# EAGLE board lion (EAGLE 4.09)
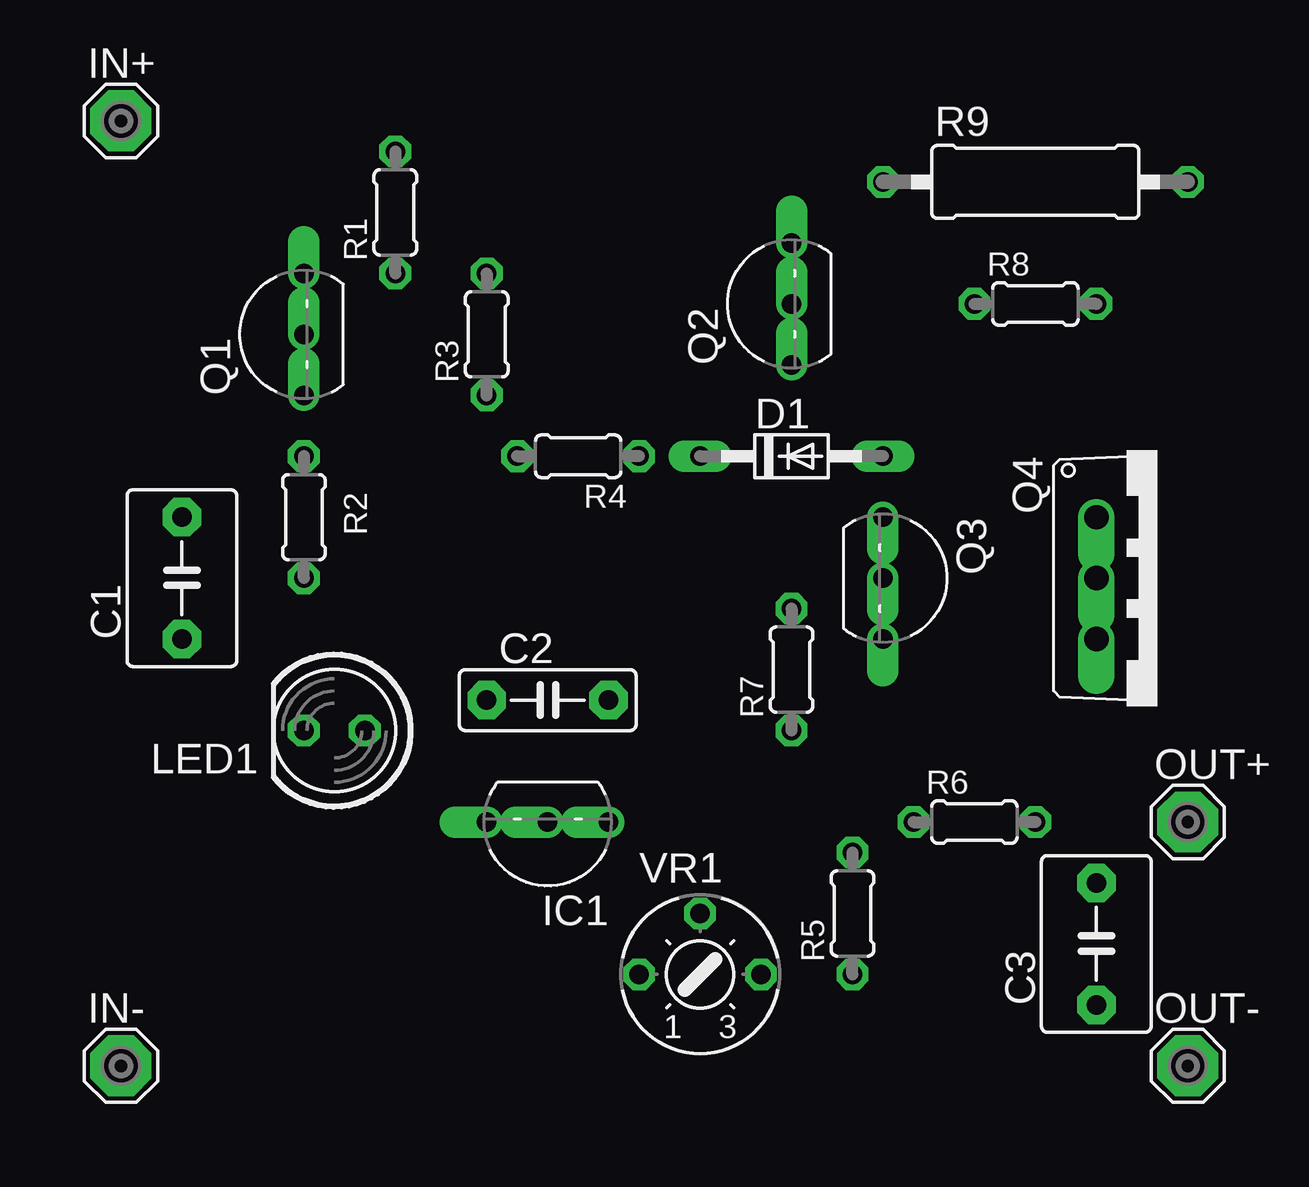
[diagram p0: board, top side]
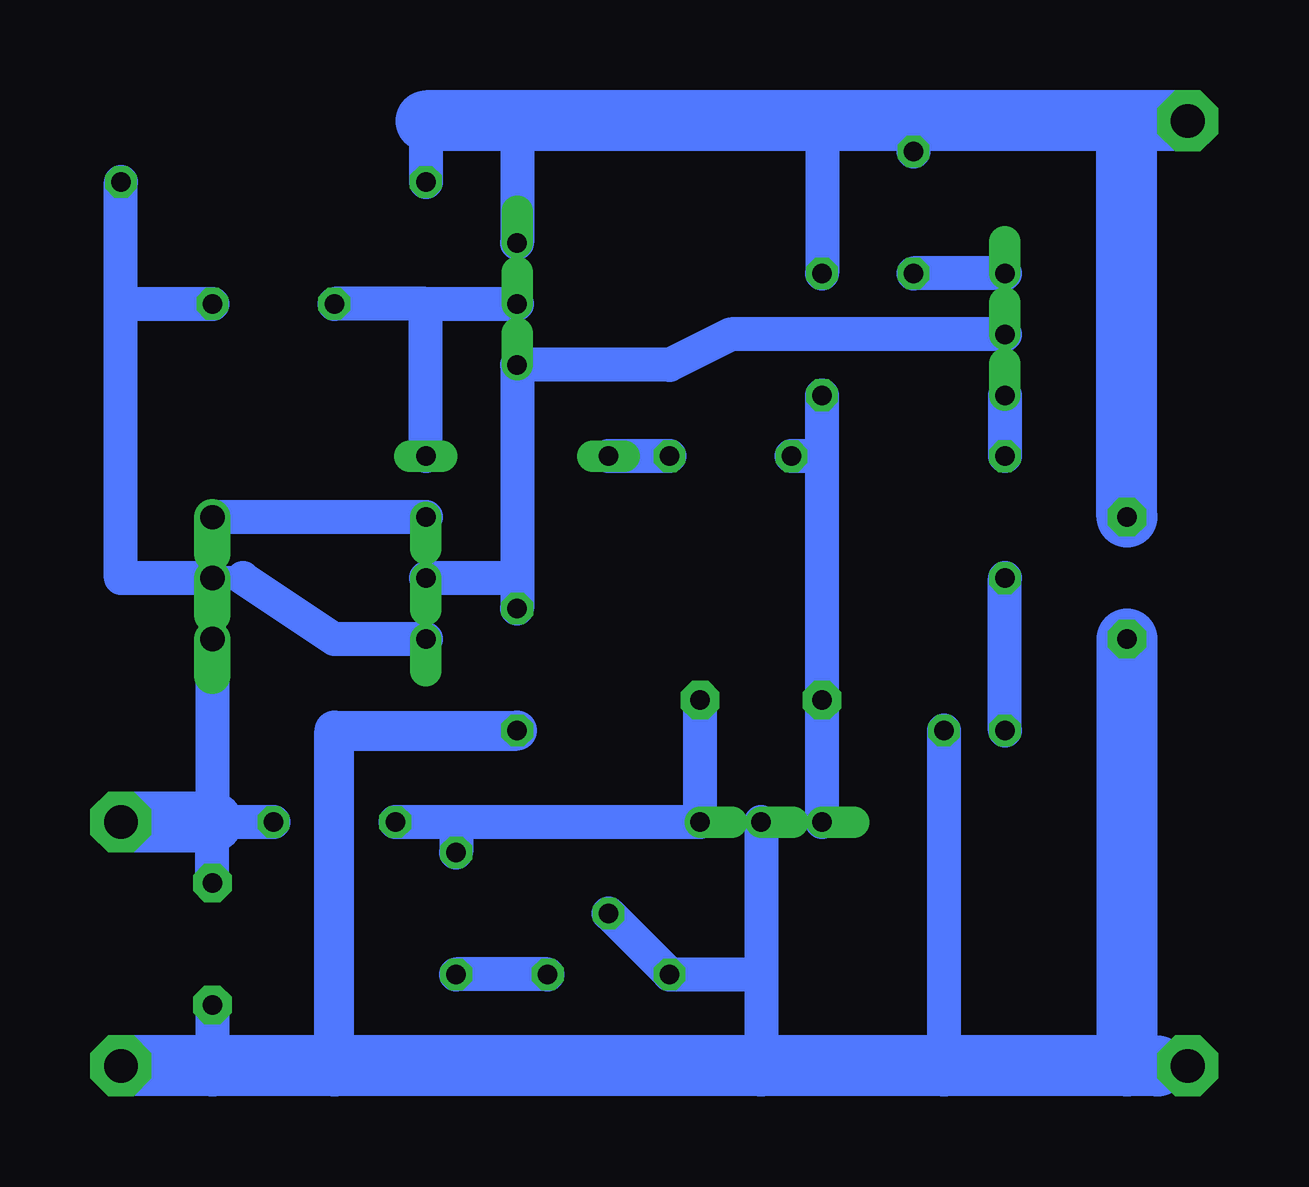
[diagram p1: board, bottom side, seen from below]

No outline drawn. Coordinates in mm, seen from the top.
Copper layers used: Bottom

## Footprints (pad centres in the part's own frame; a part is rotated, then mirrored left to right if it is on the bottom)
C5B4.5 = drill 0.813 pad 1.6 octagon: 1 -2.54,0; 2 2.54,0
C5B2.5 = drill 0.813 pad 1.6 octagon: 1 -2.54,0; 2 2.54,0
DO34-7 = drill 0.813 long: A 3.81,0; C -3.81,0
TO92- = drill 0.813 offset: 1 2.54,0; 2 0,0; 3 -2.54,0
SE14 = drill 1.397 pad 2.54 octagon: MP 0,0
LED5MM = drill 0.813 octagon: A -1.27,0; K 1.27,0
TO220V = drill 1.016 offset: 1 -2.54,-2.54; 2 0,-2.54; 3 2.54,-2.54
0204/5 = drill 0.813 octagon: 1 -2.54,0; 2 2.54,0
0309/12 = drill 0.813 octagon: 1 -6.35,0; 2 6.35,0
S75P = drill 0.813 octagon: A -2.54,0; E 2.54,0; S 0,2.54

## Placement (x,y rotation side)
C1  [C5B4.5]  44.45,57.15 90 top
C2  [C5B2.5]  59.69,52.07 0 top
C3  [C5B4.5]  82.55,41.91 90 top
D1  [DO34-7]  69.85,62.23 0 top
IC1  [TO92-]  59.69,46.99 180 top
IN+  [SE14]  41.91,76.2 0 top
IN-  [SE14]  41.91,36.83 0 top
LED1  [LED5MM]  50.8,50.8 180 top
OUT+  [SE14]  86.36,46.99 0 top
OUT-  [SE14]  86.36,36.83 0 top
Q1  [TO92-]  49.53,67.31 90 top
Q2  [TO92-]  69.85,68.58 90 top
Q3  [TO92-]  73.66,57.15 270 top
Q4  [TO220V]  85.09,57.15 270 top
R1  [0204/5]  53.34,72.39 90 top
R2  [0204/5]  49.53,59.69 90 top
R3  [0204/5]  57.15,67.31 90 top
R4  [0204/5]  60.96,62.23 180 top
R5  [0204/5]  72.39,43.18 90 top
R6  [0204/5]  77.47,46.99 0 top
R7  [0204/5]  69.85,53.34 90 top
R8  [0204/5]  80.01,68.58 0 top
R9  [0309/12]  80.01,73.66 0 top
VR1  [S75P]  66.04,40.64 0 top

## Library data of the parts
C1-C3 = capacitor-wima
D1 = diode
IC1 Q1-Q4 = transistor-fet
IN+ IN- OUT+ OUT- = solpad
LED1 = led
R1-R9 = rcl
VR1 = pot

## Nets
Q1: C1.2 Q2.1 R1.2 R3.2 R9.1
S$3: Q1.1 R1.1
S$5: Q1.3 R2.2
S$7: D1.A Q2.2
S$8: Q3.1 Q4.2 R8.2 R9.2
S$9: LED1.K R2.1
S$10: Q1.2 Q2.3 Q3.2 R7.2
S$11: Q3.3 Q4.1
S$12: C2.2 IC1.3 R5.2 R6.1
S$13: C1.1 C3.1 IC1.2 LED1.A R7.1 VR1.A VR1.S
S$14: C3.2 Q4.3 R6.2
S$15: R5.1
S$17: D1.C R4.1
S$18: C2.1 IC1.1 R3.1 R4.2

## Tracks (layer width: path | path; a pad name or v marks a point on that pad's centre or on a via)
Q1
  Bottom 1.422: 73.66,76.2 R9.1 | 53.34,76.2 R1.2 | 57.15,76.2 R3.2 | 69.85,76.2 Q2.1
  Bottom 2.54: 41.91,76.2 44.45,76.2 | 44.45,76.2 53.34,76.2 57.15,76.2 69.85,76.2 73.66,76.2 | C1.2 44.45,76.2
S$3
  Bottom 1.422: Q1.1 R1.1
S$5
  Bottom 1.422: Q1.3 R2.2
S$7
  Bottom 1.422: 73.66,68.58 Q2.2 | D1.A 73.66,68.58 | 73.66,68.58 77.47,68.58
S$8
  Bottom 1.016: 81.28,57.15 Q4.2
  Bottom 1.422: Q3.1 77.47,54.61 81.28,57.15 | 86.36,68.58 R8.2 | 86.36,68.58 86.36,57.15 Q4.2 | 86.36,68.58 R9.2
S$9
  Bottom 1.422: LED1.K R2.1
S$10
  Bottom 1.422: Q1.2 60.96,67.31 63.5,66.04 Q2.3 69.85,57.15 | 69.85,57.15 Q3.2 | 69.85,57.15 R7.2
S$11
  Bottom 1.422: Q3.3 Q4.1
S$12
  Bottom 1.422: 72.39,46.99 IC1.3 C2.2 | 72.39,46.99 R6.1 | 72.39,46.99 R5.2
S$13
  Bottom 1.422: VR1.S VR1.A 59.69,40.64 | IC1.2 59.69,40.64 | 59.69,40.64 59.69,36.83 | LED1.A 52.07,36.83 | C3.1 82.55,36.83
  Bottom 1.676: R7.1 77.47,50.8 77.47,36.83
  Bottom 2.54: 43.18,36.83 44.45,36.83 | 44.45,36.83 52.07,36.83 59.69,36.83 77.47,36.83 82.55,36.83 86.36,36.83 | C1.1 44.45,36.83
S$14
  Bottom 1.422: R6.2 82.55,46.99 | Q4.3 82.55,46.99 | C3.2 82.55,46.99
  Bottom 2.54: 82.55,46.99 86.36,46.99
S$15
  Bottom 1.422: 68.58,40.64 R5.1
S$17
  Bottom 1.422: R4.1 D1.C
S$18
  Bottom 1.422: 57.15,62.23 R3.1 | IC1.1 C2.1 57.15,62.23 | 57.15,62.23 R4.2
